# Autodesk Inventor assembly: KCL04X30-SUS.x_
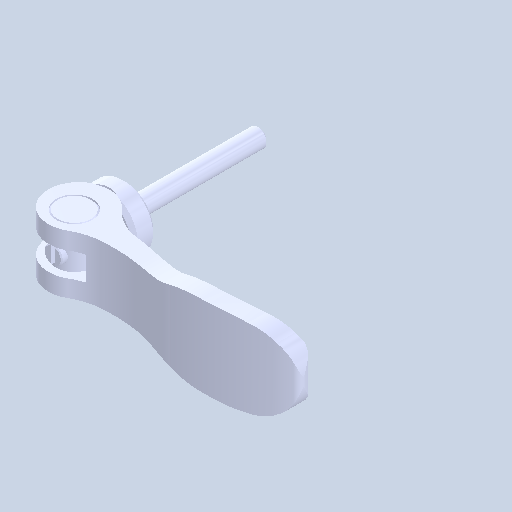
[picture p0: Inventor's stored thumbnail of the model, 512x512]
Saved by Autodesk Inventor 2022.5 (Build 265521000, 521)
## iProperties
Created: 2024-08
Part Number: KCL04X30-SUS.x_
Document SubType Name: Assembly
Designer: ImaoCorp
Author: ImaoCorp
Sending System: SOLIDWORKS 2022-2022290
MC: AMD64
MC_MODEL: Intel64 Family 6 Model 60 Stepping 3, GenuineIntel
OS: Windows_NT
FRU: Parasolid Version 33.1, build 260,  4-25-2022
FORMAT: text
GUISE: transmit
KEY: FILEKCL04X30-SUS.x_t
DATE: Thu Aug 29 10:48:04 2024
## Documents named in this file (5)
- Y:\5.更新分\2024年対応\1001_KCL\データ\kcl04x30-sus\KCL04X30-SUS.x_.iam
- Y:\5.更新分\2024年対応\1001_KCL\データ\kcl04x30-sus\KCL4X30-SUS_01.ipt
- Y:\5.更新分\2024年対応\1001_KCL\データ\kcl04x30-sus\KCL4X30-SUS_02.ipt
- Y:\5.更新分\2024年対応\1001_KCL\データ\kcl04x30-sus\KCL4X30-SUS_03.ipt
- Y:\5.更新分\2024年対応\1001_KCL\データ\kcl04x30-sus\KCL4X30-SUS_04.ipt
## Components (4 placed, 4 different names)
1. KCL4X30-SUS_01
2. KCL4X30-SUS_02
3. KCL4X30-SUS_03
4. KCL4X30-SUS_04
